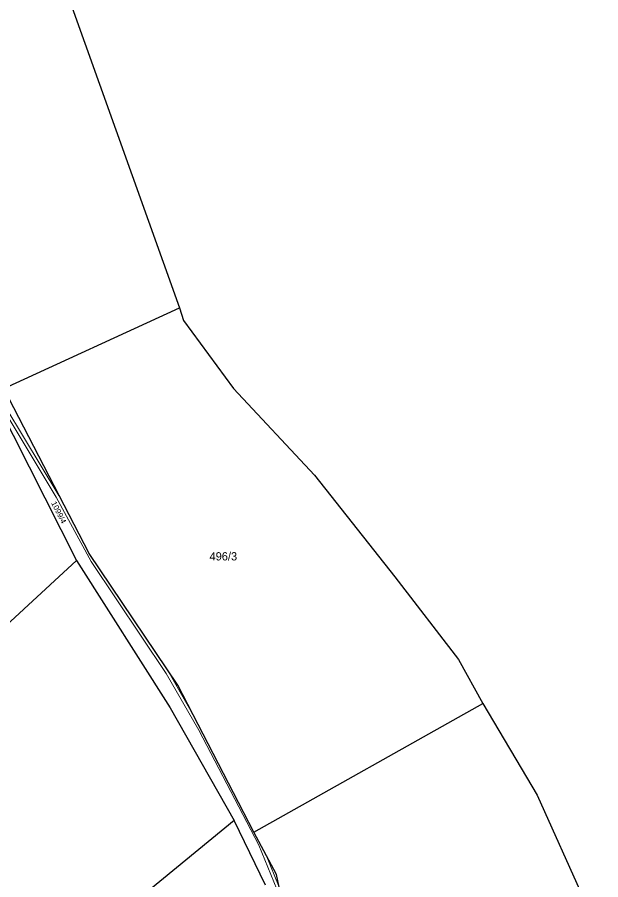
# Model space of a CAD drawing. Extents: x -694609 to -690140, y -1033292 to -1029794.
# Drawn here: x -691085 to -690964.6, y -1031463.5 to -1031285.6 of the extents above; entities that cross this region are included whole.
import ezdxf
from ezdxf.enums import TextEntityAlignment as Align

# ---------------------------------------------------------------- set-up
doc = ezdxf.new("R2010")
doc.units = 0
doc.header["$LTSCALE"] = 0.68
doc.layers.add('1', color=7, linetype='Continuous', lineweight=25)
doc.layers.add('13', color=7, linetype='Continuous', lineweight=13)
doc.layers.add('2', color=7, linetype='Continuous')

msp = doc.modelspace()

# ---------------------------------------------------------------- linework, layer by layer
at = {"layer": '1'}
for p, q in [((-691081.27, -1031262.14), (-691051.48, -1031345.52)), ((-691087.74, -1031362.19), (-691051.48, -1031345.52)), ((-691051.48, -1031345.52), (-691050.64, -1031348.17)), ((-691050.64, -1031348.17), (-691040.32, -1031362.15)), ((-691095.47, -1031352.79), (-691072.76, -1031397.63)), ((-691070.14, -1031396.24), (-691087.74, -1031362.19)), ((-691040.32, -1031362.15), (-691023.61, -1031380.02)), ((-691023.61, -1031380.02), (-691007.06, -1031401.04)), ((-691051.84, -1031423.4), (-691070.14, -1031396.24)), ((-691184.09, -1031500.82), (-691072.76, -1031397.63)), ((-691072.76, -1031397.63), (-691053.39, -1031428.07)), ((-691007.06, -1031401.04), (-690993.94, -1031418.11)), ((-690993.94, -1031418.11), (-690988.92, -1031427.19)), ((-691036.15, -1031453.73), (-691051.84, -1031423.4)), ((-691036.15, -1031453.73), (-690988.92, -1031427.19)), ((-690988.92, -1031427.19), (-690977.69, -1031446.05)), ((-691053.39, -1031428.07), (-691040.21, -1031451.34)), ((-690977.69, -1031446.05), (-690964.56, -1031475.26)), ((-691040.21, -1031451.34), (-691144, -1031536.13)), ((-691033.73, -1031464.62), (-691040.21, -1031451.34)), ((-691031.48, -1031462.45), (-691036.15, -1031453.73)), ((-691024.42, -1031495.33), (-691031.48, -1031462.45))]:
    msp.add_line(p, q, dxfattribs=at)
at = {"layer": '13'}
for points in [[(-691087.84, -1031366.35), (-691076.93, -1031384.58), (-691069.69, -1031397.88), (-691054.24, -1031420.95), (-691047.5, -1031432.67), (-691035.1, -1031456.41), (-691031.4, -1031465.49)], [(-691030.91, -1031465.09), (-691033.62, -1031458.46), (-691036.15, -1031453.73), (-691049.12, -1031428.66), (-691053.91, -1031420.33), (-691070.14, -1031396.24), (-691074.69, -1031387.44), (-691076.41, -1031384.28), (-691087.32, -1031366.07)]]:
    msp.add_lwpolyline(points, dxfattribs=at)

# ---------------------------------------------------------------- texts
at = {"layer": '2', "width": 1.05}
msp.add_text('1099/4', height=1.14, rotation=297, dxfattribs=at).set_placement((-691076.8864, -1031387.9812), align=Align.CENTER)
at = {"layer": '2'}
msp.add_text('496/3', height=1.7, dxfattribs=at).set_placement((-691042.44, -1031397.645), align=Align.CENTER)

doc.saveas('drawing.dxf')
